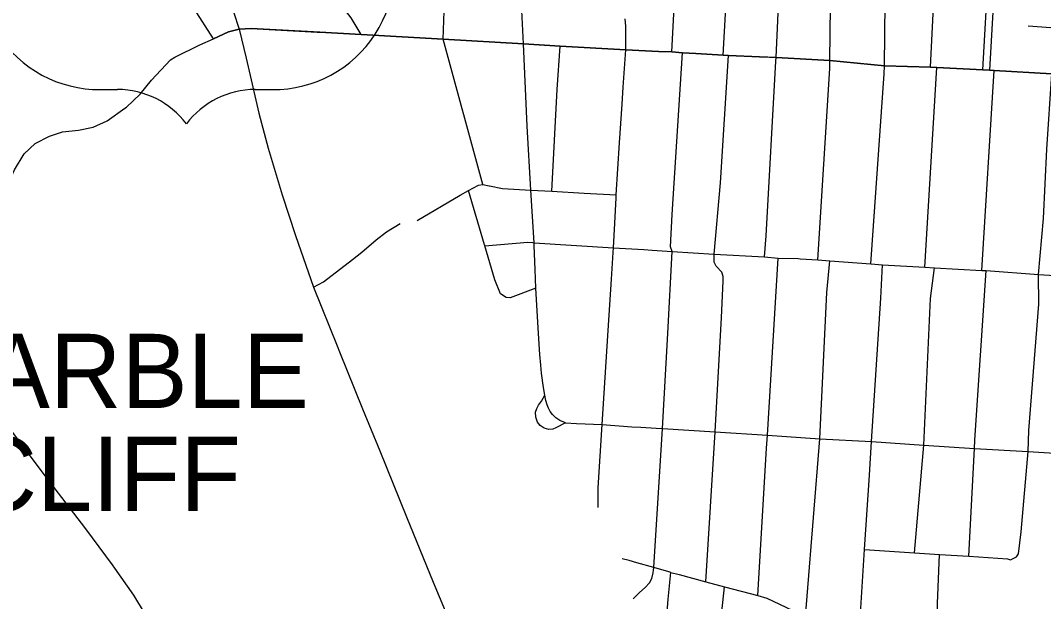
# Model space of a CAD drawing. Extents: x 1755200 to 1902939, y 644115 to 788070.
# Drawn here: x 1808159 to 1815056, y 721334 to 725250 of the extents above; entities that cross this region are included whole.
import ezdxf

# ---------------------------------------------------------------- set-up
doc = ezdxf.new("R2010")
doc.units = 0
for name, color, linetype in [('GM_X_City_Street', 7, 'Continuous'), ('GM_X_Corporation_Text', 7, 'Continuous'), ('GM_X_Township', 7, 'Continuous'), ('GM_X_US_Route', 7, 'Continuous'), ('GM_X_US_Shield', 7, 'Continuous')]:
    doc.layers.add(name, color=color, linetype=linetype)

msp = doc.modelspace()

# ---------------------------------------------------------------- linework, layer by layer
at = {"layer": 'GM_X_City_Street'}
for points in [[(1812550.4, 725037.5), (1812601.8, 726027.8), (1812631.3, 726120.7), (1812753.8, 726534.7), (1812801.2, 726760.9), (1812819.8, 726885.2), (1812843.7, 727092), (1812853.1, 727383.9), (1812840.9, 727455.3), (1812841.5, 727702.1), (1812824, 727839), (1812790.5, 728004), (1812744.9, 728148.5), (1812699.3, 728274.8), (1812593.6, 728495.3), (1812424.6, 728864.5)], [(1811008.9, 725124.1), (1811020.7, 725440.7), (1811041.6, 725804.4), (1811046.8, 726015.3), (1811047.7, 726169.8), (1811041.6, 726300.9), (1811035.5, 726383.4), (1811020.7, 726527.5), (1810994.7, 726715.8), (1810982.5, 726774)], [(1808795.1, 721558), (1808779, 721580.7), (1808599.2, 721824.2), (1808306, 722208.8), (1807985.2, 722632.1), (1807670.9, 723038.7), (1807377.6, 723432), (1806989.8, 723953.5), (1806147.3, 725108.1), (1805654.1, 725776.1), (1805409.9, 726117.9), (1805269.4, 726309.7), (1805131.2, 726507.4), (1805081.3, 726573.7), (1805021.7, 726645), (1804975, 726686.2)], [(1811550.2, 725092.6), (1811535.5, 725409.4), (1811513.8, 725780.1), (1811504.3, 725987.6), (1811493, 726224.5), (1811479.1, 726486.7), (1811477.6, 726513.6)], [(1810457, 725154.8), (1810389.1, 725266.5), (1810316.8, 725360.7), (1810200.7, 725476.7), (1810091.2, 725566.5), (1809924.8, 725702.3), (1809644.4, 725973.9), (1809377.3, 726254.2)], [(1813185.5, 723798.4), (1813251.8, 724975), (1813252.9, 725000.2), (1813295.5, 725950.9), (1813298.8, 725987), (1813306.6, 726044.3), (1813317.6, 726109.1), (1813340.5, 726212.7)], [(1813535.6, 723637.6), (1813615.3, 724925.3), (1813615.9, 724979.6), (1813621.6, 725527.5), (1813646.5, 725933.2), (1813647.8, 725967.9), (1813649.5, 726007.8), (1813659.1, 726079.9), (1813675.6, 726197.9)], [(1813892.2, 723609), (1813982.7, 724889.7), (1813984.1, 724943.3), (1813992.4, 725796), (1814001.1, 725949.7), (1814014.1, 726084.2), (1814024.5, 726182.3)], [(1814293.9, 724935.6), (1814343.1, 725930.6), (1814353.5, 726116.3)], [(1812897.4, 725016.9), (1812947.3, 725934), (1812950.7, 726008.7), (1812951.3, 726011.4)], [(1814648, 724917.3), (1814684.5, 725588.3), (1814700.5, 725904.1)], [(1812240.6, 725106.6), (1812239.5, 725211.5), (1812236, 725261)], [(1808863.8, 724658.3), (1808874.1, 724665.6), (1808965, 724752.4), (1809041.9, 724847), (1809171.7, 724985.2), (1809198.9, 725002.1), (1809368.4, 725085.7), (1809460.3, 725127.1), (1809562.7, 725173.9), (1809632.7, 725192.1)], [(1809632.7, 725192.1), (1809714.2, 725196.5), (1810159.7, 725171.6)], [(1814952.9, 725212.7), (1815561, 725169.5), (1815953.4, 725141.7), (1816973, 725124.9)], [(1810159.7, 725171.6), (1810177.9, 725170.6), (1810457, 725154.8), (1811008.9, 725124.1), (1811550.2, 725092.6), (1811796.8, 725076.1), (1812241.2, 725051.8), (1812460, 725041.7), (1812478.4, 725040.8)], [(1811277.2, 724143.3), (1811008.9, 725124.1)], [(1811622.4, 723731.8), (1811621.4, 723752.3), (1811600.6, 724105.6), (1811575.4, 724536.9), (1811550.2, 725092.6)], [(1811742.1, 724099.5), (1811776.5, 724784.4), (1811796.8, 725076.1)], [(1812215, 724685.6), (1812222.6, 724800.3), (1812241.2, 725051.8), (1812240.6, 725106.6)], [(1812478.4, 725040.8), (1812550.4, 725037.5), (1812621.9, 725031.4), (1812712.9, 725026.6), (1812897.4, 725016.9), (1812932.6, 725012.8), (1813140.5, 725004.6), (1813163.5, 725003.7)], [(1812486.9, 722499.7), (1812523.3, 723140.4), (1812553.7, 723692.4), (1812540.7, 723725.4), (1812553.7, 723943.3), (1812621.9, 725031.4)], [(1812778.9, 721467.3), (1812841.8, 722477.5), (1812886.3, 723247.8), (1812895.8, 723492.7), (1812895.8, 723524.6), (1812887.8, 723553.2), (1812849.6, 723594.6), (1812836.9, 723621.7), (1812836.9, 723674.2), (1812879, 724155.2), (1812932.6, 725012.8)], [(1813163.5, 725003.7), (1813252.9, 725000.2), (1813615.9, 724979.6), (1813984.1, 724943.3), (1814293.9, 724935.6), (1814336.4, 724933), (1814648, 724917.3), (1814691.9, 724915), (1814724.3, 724913.2), (1815112.2, 724889.3), (1815528.3, 724855.6), (1815939.4, 724829.2), (1816951.7, 724754.5), (1817466.6, 724716.2), (1817784.7, 724698.3), (1818114.7, 724671.6), (1818406, 724647.8), (1818441.7, 724647.8), (1818582.9, 724639.3), (1819027.7, 724609.4), (1819097.3, 724604.7), (1819495.6, 724577.5)], [(1814256.7, 723588.3), (1814336.4, 724933)], [(1814641.1, 723565.2), (1814724.3, 724913.2)], [(1815023.8, 723337.6), (1815022.3, 723538.9), (1815055.7, 723915.5), (1815078.7, 724381.5), (1815112.2, 724889.3)], [(1807377.6, 723432), (1807538.1, 723556.2), (1807744.9, 723707.3), (1807856.7, 723783.8), (1807900.1, 723827.3), (1807937.4, 723862.4), (1807970.5, 723910), (1807999.4, 723963.8), (1808063.6, 724102.5), (1808096.7, 724193.5), (1808119.4, 724243.1), (1808184.8, 724350.9), (1808257.8, 724421.7), (1808355, 724470.3), (1808443.4, 724499.1), (1808549.5, 724510.1), (1808649.4, 724530.2), (1808744.2, 724573.6), (1808863.8, 724658.3)], [(1812175, 724054), (1812176.1, 724075.2), (1812197.8, 724424.2), (1812215, 724685.6)], [(1810833.7, 723902.2), (1811123.3, 724072.5), (1811180.2, 724103), (1811247.2, 724139.5), (1811277.2, 724143.3), (1811320.1, 724134.6), (1811321.2, 724134.4)], [(1811288.7, 723735.4), (1811288.2, 723737.1), (1811180.2, 724103)], [(1811321.2, 724134.4), (1811409.8, 724116.4), (1811600.6, 724105.6), (1811742.1, 724099.5), (1811960, 724086.5), (1812176.1, 724075.2)], [(1812154.3, 723685.4), (1812156.2, 723718.5), (1812166.6, 723883.4), (1812175, 724054)], [(1810133.6, 723453.4), (1810203, 723489), (1810396.6, 723639.1), (1810460.8, 723689.5), (1810556.3, 723771.1), (1810627.5, 723825.8), (1810718.6, 723882.2)], [(1811290, 723730.9), (1811579.8, 723755.8), (1811614.5, 723752.9)], [(1811614.5, 723752.9), (1811621.4, 723752.3), (1812156.2, 723718.5)], [(1813174.3, 723656.7), (1813185.5, 723798.4)], [(1811634.4, 723445), (1811460.7, 723380.1), (1811432.6, 723384), (1811396.3, 723407.8), (1811357.7, 723501.9), (1811290, 723730.9), (1811288.7, 723735.4)], [(1811834.1, 722538.8), (1811795.9, 722553.5), (1811769.5, 722571.9), (1811746.4, 722595.2), (1811730.8, 722614.3), (1811718.7, 722637.3), (1811710, 722658.6), (1811701.3, 722688.1), (1811694.3, 722724.5), (1811684.8, 722777.5), (1811672.7, 722872.1), (1811667.4, 722925.9), (1811661.4, 722998), (1811651.8, 723140.4), (1811634.4, 723445), (1811630.1, 723571.7), (1811622.4, 723731.8)], [(1812081.5, 722527.5), (1812120.6, 723161.2), (1812144, 723507.5), (1812154.3, 723685.4)], [(1812156.2, 723718.5), (1812361.9, 723706.3), (1812418.5, 723702.2)], [(1812418.5, 723702.2), (1812553.7, 723692.4), (1812836.9, 723674.2), (1813174.3, 723656.7), (1813268.3, 723648.7), (1813402, 723644.7), (1813415.4, 723644)], [(1813129.6, 721374.4), (1813187.9, 722367.3), (1813194.6, 722454.3), (1813268.3, 723648.7)], [(1813415.4, 723644), (1813535.6, 723637.6), (1813616, 723629.7), (1813892.2, 723609), (1813970.2, 723602.6), (1814256.7, 723588.3), (1814321.1, 723583.5), (1814641.1, 723565.2), (1814668.9, 723564.4), (1815022.3, 723538.9), (1815428.1, 723513.4)], [(1813594.8, 723416.9), (1813616, 723629.7)], [(1813959, 723379.1), (1813970.2, 723602.6)], [(1814294.3, 723376.9), (1814321.1, 723583.5)], [(1814552.2, 721638.8), (1814590.7, 722366.3), (1814593.6, 722422), (1814668.9, 723564.4)], [(1813398.7, 720526.3), (1813450.9, 721232.9), (1813462.2, 721369.8), (1813547.3, 722431.1), (1813594.8, 723416.9)], [(1813818.3, 721182), (1813850.4, 721683.9), (1813882.6, 722186.7), (1813897.1, 722412.4), (1813959, 723379.1)], [(1814186, 721662.3), (1814250.3, 722387), (1814294.3, 723376.9)], [(1814875, 721635.5), (1814888.6, 721655.9), (1814905.2, 721804.8), (1814953.4, 722345.2), (1814957.5, 722486.7), (1815023.8, 723337.6)], [(1811834.1, 722538.8), (1811769, 722504.1), (1811747.3, 722495.4), (1811720.4, 722494.5), (1811689.1, 722503.2), (1811663.1, 722521.4), (1811644.9, 722543.1), (1811632.7, 722576.1), (1811631.8, 722610), (1811641.4, 722636), (1811651.8, 722657.7), (1811670.9, 722685.5), (1811694.3, 722724.5)], [(1811834.1, 722538.8), (1811907.9, 722534.4), (1812081.5, 722527.5)], [(1812054.6, 721968.5), (1812054.6, 722099.5), (1812081.5, 722527.5)], [(1812081.5, 722527.5), (1812281.9, 722512.5), (1812341.5, 722508.8)], [(1812341.5, 722508.8), (1812445.6, 722502.3)], [(1812428.2, 721563.7), (1812486.9, 722499.7)], [(1812445.6, 722502.3), (1812486.9, 722499.7), (1812841.8, 722477.5), (1813194.6, 722454.3), (1813547.3, 722431.1), (1813897.1, 722412.4), (1814250.3, 722387), (1814590.7, 722366.3), (1814953.4, 722345.2), (1815345.5, 722319.7)], [(1813850.4, 721683.9), (1814186, 721662.3), (1814355.5, 721651.4), (1814552.2, 721638.8), (1814813.1, 721622), (1814833.4, 721614.4), (1814875, 721635.5)], [(1812428.2, 721563.7), (1812315.3, 721594.1), (1812263.3, 721609.7), (1812216.5, 721622.8)], [(1814172.9, 720390.5), (1814173, 720390.9), (1814178.2, 720440.4), (1814200.4, 720961.2), (1814207.1, 721017.6), (1814299.6, 721182.4), (1814340.1, 721253.6), (1814341.5, 721292.9), (1814342.5, 721319.9), (1814355.5, 721651.4)], [(1809957.5, 719201.3), (1809776.8, 719433.6), (1809579, 719687.3), (1809497.2, 719814.2), (1809436.9, 719925.9), (1809398.2, 720003.3), (1809351.5, 720103.2), (1809303.9, 720261.2), (1809284.4, 720354.3), (1809232.5, 720551.3), (1809163.3, 720815.3), (1809107, 721003.6), (1809048.6, 721150.8), (1808994.5, 721259), (1808923.1, 721378.1), (1808795.1, 721558)], [(1812290.2, 721352.8), (1812333.6, 721396.2), (1812371.8, 721428.3), (1812400.4, 721459.5), (1812416, 721489.9), (1812425.6, 721528.1), (1812428.2, 721563.7)], [(1812529.2, 721534.1), (1812428.2, 721563.7)], [(1812492.6, 720810.6), (1812492.4, 720811.1), (1812489, 720846.7), (1812489, 720884.9), (1812526.3, 721350.1), (1812543.7, 721529.8), (1812529.2, 721534.1)], [(1812543.7, 721529.8), (1812600.9, 721515.9), (1812778.9, 721467.3), (1812906.5, 721432.6), (1813129.6, 721374.4), (1813190.3, 721356.2), (1813450.9, 721232.9), (1813815, 721130.9)], [(1812819.7, 720634), (1812906.5, 721432.6)]]:
    msp.add_lwpolyline(points, dxfattribs=at)
at = {"layer": 'GM_X_Township'}
for points in [[(1814730.6, 725585.1), (1814691.9, 724915), (1814648, 724917.4), (1814336.4, 724933), (1814293.9, 724935.6), (1813984.1, 724943.3), (1813615.9, 724979.6), (1813252.9, 725000.2), (1813140.5, 725004.6), (1812932.6, 725012.8), (1812897.4, 725016.9), (1812713, 725026.6), (1812621.9, 725031.4), (1812550.4, 725037.5), (1812460, 725041.7), (1812241.2, 725051.8), (1811796.8, 725076.1), (1811550.2, 725092.6), (1811008.9, 725124.1), (1810457, 725154.8), (1810177.9, 725170.6), (1809714.2, 725196.5), (1809632.7, 725192.1), (1809562.7, 725173.9), (1809460.3, 725127.1), (1809195.9, 725542.3)], [(1819495.6, 724577.5), (1819097.4, 724604.6), (1819027.7, 724609.4), (1818582.9, 724639.3), (1818441.7, 724647.8), (1818406.1, 724647.8), (1818114.7, 724671.6), (1817784.7, 724698.3), (1817466.6, 724716.2), (1816951.7, 724754.4), (1815939.4, 724829.2), (1815528.3, 724855.6), (1815112.3, 724889.3), (1814724.3, 724913.2), (1814691.9, 724915)], [(1814691.9, 724915), (1814724.3, 724913.2)]]:
    msp.add_lwpolyline(points, dxfattribs=at)
at = {"layer": 'GM_X_US_Route'}
for points in [[(1809423.7, 725672.5), (1809490.4, 725538.9), (1809558, 725396.9), (1809595.4, 725307.5), (1809632.7, 725192.1), (1809680.4, 724995), (1809767.2, 724626.1), (1809829.7, 724390), (1809924.4, 724074.9), (1810012.9, 723801.5), (1810133.6, 723453.4), (1810294.1, 723056.4), (1810309.8, 723017.5)], [(1810309.8, 723017.5), (1810464.3, 722633.1), (1810581.5, 722350.1), (1810762, 721904.8), (1810940.9, 721464.7), (1811021.6, 721271.1), (1811074, 721162.9), (1811135.7, 721044), (1811208, 720910.1)]]:
    msp.add_lwpolyline(points, dxfattribs=at)
at = {"layer": 'GM_X_US_Shield'}
for p, q in [((1808698, 724784.5), (1808814, 724784.5)), ((1809742.2, 724784.5), (1809858.2, 724784.5))]:
    msp.add_line(p, q, dxfattribs=at)
for centre, radius, start, end in [((1808689, 725596.5), 812.1, 154.83192, 270.63826), ((1809867.2, 725596.5), 812.1, 269.36174, 25.16808), ((1808814, 724204.4), 580.1, 36.8699, 90), ((1809742.2, 724204.4), 580.1, 90, 143.1301)]:
    msp.add_arc(centre, radius, start, end, dxfattribs=at)

# ---------------------------------------------------------------- texts
at = {"layer": 'GM_X_Corporation_Text'}
for s, p in [('MARBLE', (1807354.2, 722638.2)), ('CLIFF', (1807787.6, 721944.1))]:
    msp.add_text(s, height=500, rotation=0.00001, dxfattribs=at).set_placement(p)

doc.saveas('drawing.dxf')
